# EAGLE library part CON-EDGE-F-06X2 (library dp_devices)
Female 6x2 Edge connector
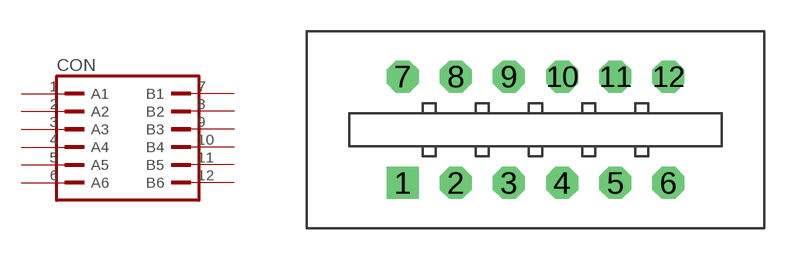
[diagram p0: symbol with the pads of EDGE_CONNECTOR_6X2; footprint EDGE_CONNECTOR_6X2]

Designator prefix CON

## CON-EDGE-F-06X2  [EDGE_CONNECTOR_6X2]
1  A1  pas
2  A2  pas
3  A3  pas
4  A4  pas
5  A5  pas
6  A6  pas
7  B1  pas
8  B2  pas
9  B3  pas
10  B4  pas
11  B5  pas
12  B6  pas

## Footprint EDGE_CONNECTOR_6X2 (pad centres in mm)
0.100 x 0.200 inch pitch Edge Connector with no mounting ear
drill 1.02 square: 1 -6.35,-2.54
drill 1.02 octagon: 2 -3.81,-2.54; 3 -1.27,-2.54; 4 1.27,-2.54; 5 3.81,-2.54; 6 6.35,-2.54; 7 -6.35,2.54; 8 -3.81,2.54; 9 -1.27,2.54; 10 1.27,2.54; 11 3.81,2.54; 12 6.35,2.54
